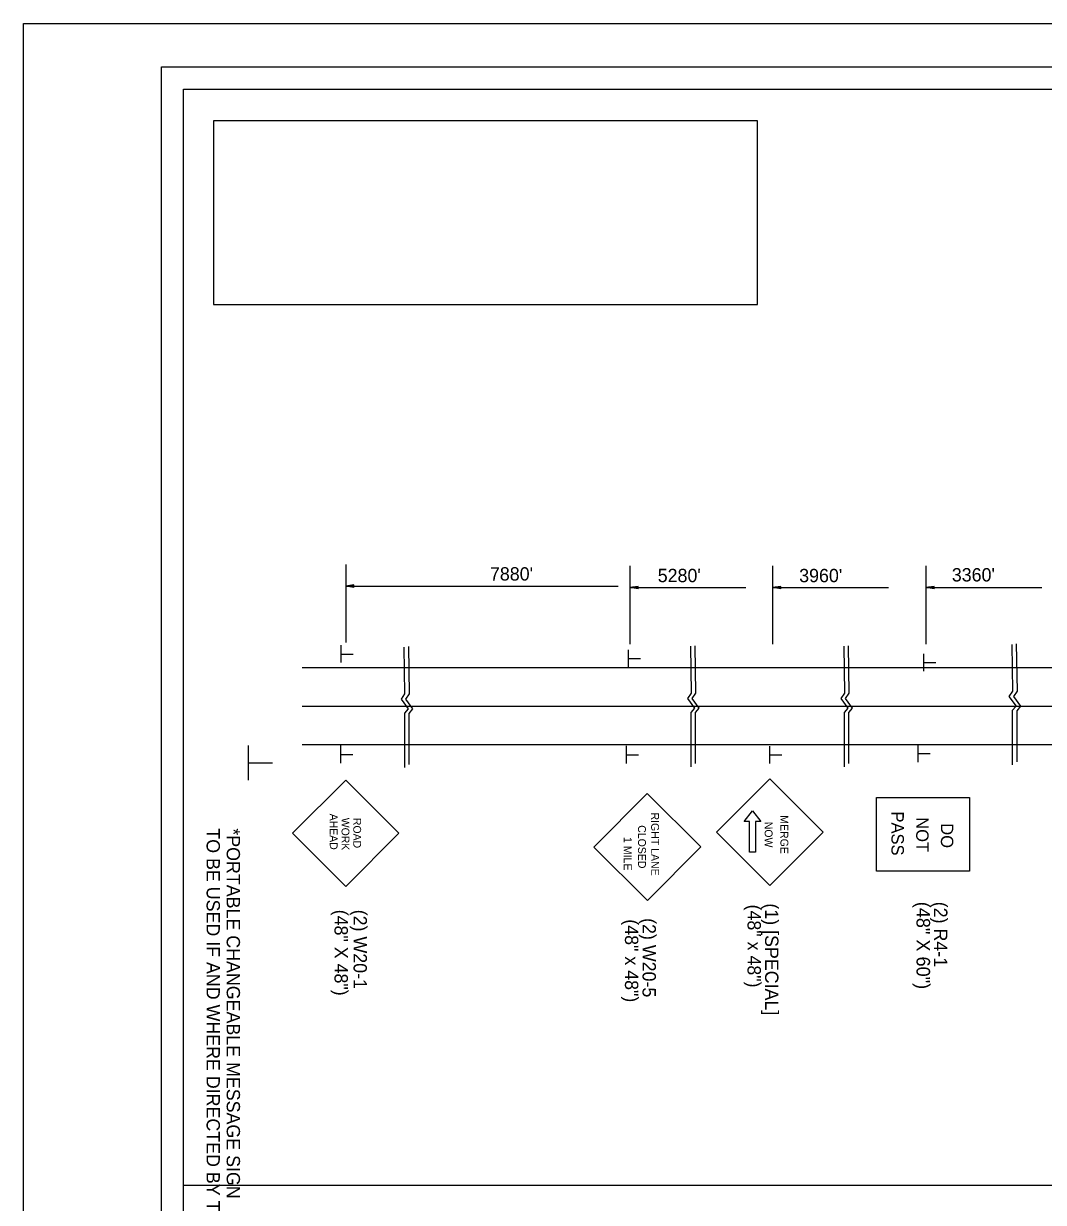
# Model space of a CAD drawing. Extents: x -500 to 213, y 382723 to 382830.
# Drawn here: x -316.3 to -270.4, y 382776.7 to 382829.8 of the extents above; entities that cross this region are included whole.
import ezdxf

# ---------------------------------------------------------------- set-up
doc = ezdxf.new("R2010")
doc.units = 0
for name, color, linetype in [('Default', 7, 'Continuous'), ('R_Border', 7, 'Continuous'), ('R_Draft', 7, 'Continuous'), ('R_No Plot', 7, 'Continuous')]:
    doc.layers.add(name, color=color, linetype=linetype)

msp = doc.modelspace()

# ---------------------------------------------------------------- linework, layer by layer
at = {"layer": 'Default'}
for p, q in [((-301.787, 382805.446), (-301.787, 382801.925)), ((-288.995, 382805.379), (-288.995, 382801.858)), ((-282.579, 382805.379), (-282.579, 382801.858)), ((-275.679, 382805.379), (-275.679, 382801.858)), ((-301.412, 382804.523), (-301.787, 382804.466)), ((-301.787, 382804.466), (-289.524, 382804.466)), ((-301.412, 382804.41), (-301.787, 382804.466)), ((-301.412, 382804.513), (-301.725, 382804.466)), ((-301.412, 382804.42), (-301.725, 382804.466)), ((-301.412, 382804.504), (-301.66, 382804.466)), ((-301.412, 382804.429), (-301.66, 382804.466)), ((-301.412, 382804.494), (-301.598, 382804.466)), ((-301.412, 382804.439), (-301.598, 382804.466)), ((-301.412, 382804.485), (-301.534, 382804.466)), ((-301.412, 382804.448), (-301.534, 382804.466)), ((-301.412, 382804.475), (-301.472, 382804.466)), ((-301.412, 382804.458), (-301.472, 382804.466)), ((-301.412, 382804.41), (-301.412, 382804.523)), ((-288.62, 382804.456), (-288.995, 382804.4)), ((-288.995, 382804.4), (-283.776, 382804.4)), ((-288.62, 382804.344), (-288.995, 382804.4)), ((-288.62, 382804.447), (-288.933, 382804.4)), ((-288.62, 382804.353), (-288.933, 382804.4)), ((-288.62, 382804.437), (-288.868, 382804.4)), ((-288.62, 382804.363), (-288.868, 382804.4)), ((-288.62, 382804.428), (-288.806, 382804.4)), ((-288.62, 382804.372), (-288.806, 382804.4)), ((-288.62, 382804.418), (-288.742, 382804.4)), ((-288.62, 382804.382), (-288.742, 382804.4)), ((-288.62, 382804.409), (-288.679, 382804.4)), ((-288.62, 382804.391), (-288.679, 382804.4)), ((-288.62, 382804.344), (-288.62, 382804.456)), ((-282.204, 382804.456), (-282.579, 382804.4)), ((-282.579, 382804.4), (-277.36, 382804.4)), ((-282.204, 382804.344), (-282.579, 382804.4)), ((-282.204, 382804.447), (-282.517, 382804.4)), ((-282.204, 382804.353), (-282.517, 382804.4)), ((-282.204, 382804.437), (-282.452, 382804.4)), ((-282.204, 382804.363), (-282.452, 382804.4)), ((-282.204, 382804.428), (-282.39, 382804.4)), ((-282.204, 382804.372), (-282.39, 382804.4)), ((-282.204, 382804.418), (-282.326, 382804.4)), ((-282.204, 382804.382), (-282.326, 382804.4)), ((-282.204, 382804.409), (-282.263, 382804.4)), ((-282.204, 382804.391), (-282.263, 382804.4)), ((-282.204, 382804.344), (-282.204, 382804.456)), ((-275.304, 382804.456), (-275.679, 382804.4)), ((-275.679, 382804.4), (-270.46, 382804.4)), ((-275.304, 382804.344), (-275.679, 382804.4)), ((-275.304, 382804.447), (-275.616, 382804.4)), ((-275.304, 382804.353), (-275.616, 382804.4)), ((-275.304, 382804.437), (-275.552, 382804.4)), ((-275.304, 382804.363), (-275.552, 382804.4)), ((-275.304, 382804.428), (-275.489, 382804.4)), ((-275.304, 382804.372), (-275.489, 382804.4)), ((-275.304, 382804.418), (-275.426, 382804.4)), ((-275.304, 382804.382), (-275.426, 382804.4)), ((-275.304, 382804.409), (-275.363, 382804.4)), ((-275.304, 382804.391), (-275.363, 382804.4)), ((-275.304, 382804.344), (-275.304, 382804.456)), ((-301.995, 382801.022), (-301.995, 382801.805)), ((-289.057, 382800.814), (-289.057, 382801.597)), ((-275.77, 382800.644), (-275.77, 382801.427)), ((-301.984, 382801.412), (-301.45, 382801.412)), ((-289.046, 382801.203), (-288.512, 382801.203)), ((-275.758, 382801.033), (-275.224, 382801.033)), ((-303.739, 382800.808), (-296.862, 382800.808)), ((-296.862, 382800.808), (-293.436, 382800.808)), ((-293.436, 382800.808), (-286.775, 382800.808)), ((-286.775, 382800.808), (-279.874, 382800.808)), ((-279.874, 382800.808), (-272.48, 382800.808)), ((-272.48, 382800.808), (-266.283, 382800.808)), ((-303.739, 382799.07), (-296.785, 382799.07)), ((-296.785, 382799.07), (-292.892, 382799.07)), ((-292.892, 382799.07), (-286.775, 382799.07)), ((-286.775, 382799.07), (-279.874, 382799.07)), ((-279.874, 382799.07), (-272.434, 382799.07)), ((-272.434, 382799.07), (-266.317, 382799.07)), ((-306.167, 382795.726), (-306.167, 382797.291)), ((-303.739, 382797.331), (-296.856, 382797.331)), ((-302.005, 382796.504), (-302.005, 382797.287)), ((-296.856, 382797.331), (-293.431, 382797.331)), ((-293.431, 382797.331), (-286.775, 382797.331)), ((-289.154, 382796.488), (-289.154, 382797.27)), ((-286.775, 382797.331), (-279.874, 382797.331)), ((-282.694, 382796.482), (-282.694, 382797.265)), ((-279.874, 382797.331), (-272.388, 382797.331)), ((-276.027, 382796.539), (-276.027, 382797.321)), ((-272.388, 382797.331), (-266.351, 382797.331)), ((-301.993, 382796.893), (-301.459, 382796.893)), ((-289.142, 382796.877), (-288.608, 382796.877)), ((-282.683, 382796.871), (-282.149, 382796.871)), ((-276.016, 382796.928), (-275.482, 382796.928)), ((-306.144, 382796.505), (-305.076, 382796.505)), ((-304.173, 382793.34), (-301.784, 382795.73)), ((-299.394, 382793.34), (-301.784, 382795.73)), ((-285.101, 382793.384), (-282.7, 382795.794)), ((-280.292, 382793.393), (-282.7, 382795.794)), ((-290.618, 382792.721), (-288.216, 382795.131)), ((-285.808, 382792.729), (-288.216, 382795.131)), ((-283.851, 382793.869), (-283.476, 382794.356)), ((-283.476, 382794.356), (-283.101, 382793.869)), ((-283.617, 382793.869), (-283.851, 382793.869)), ((-283.617, 382792.49), (-283.617, 382793.869)), ((-283.335, 382793.869), (-283.335, 382792.49)), ((-283.101, 382793.869), (-283.335, 382793.869)), ((-301.784, 382790.95), (-304.173, 382793.34)), ((-301.784, 382790.95), (-299.394, 382793.34)), ((-282.691, 382790.983), (-285.101, 382793.384)), ((-282.691, 382790.983), (-280.292, 382793.393)), ((-288.208, 382790.32), (-290.618, 382792.721)), ((-288.208, 382790.32), (-285.808, 382792.729)), ((-283.335, 382792.49), (-283.617, 382792.49))]:
    msp.add_line(p, q, dxfattribs=at)
for points in [[(-299.164, 382801.724), (-299.132, 382799.621), (-299.294, 382799.379), (-298.978, 382798.946), (-299.145, 382798.747), (-299.145, 382796.301)], [(-298.965, 382801.743), (-298.932, 382799.613), (-299.095, 382799.371), (-298.778, 382798.938), (-298.945, 382798.738), (-298.945, 382796.441)], [(-286.27, 382801.758), (-286.238, 382799.654), (-286.4, 382799.413), (-286.084, 382798.98), (-286.25, 382798.78), (-286.251, 382796.334)], [(-286.07, 382801.777), (-286.038, 382799.646), (-286.2, 382799.404), (-285.884, 382798.972), (-286.051, 382798.772), (-286.051, 382796.475)], [(-279.369, 382801.758), (-279.337, 382799.654), (-279.5, 382799.413), (-279.183, 382798.98), (-279.35, 382798.78), (-279.35, 382796.334)], [(-279.17, 382801.777), (-279.138, 382799.646), (-279.3, 382799.404), (-278.984, 382798.972), (-279.15, 382798.772), (-279.151, 382796.475)], [(-271.801, 382801.844), (-271.769, 382799.741), (-271.932, 382799.499), (-271.615, 382799.066), (-271.782, 382798.867), (-271.782, 382796.421)], [(-271.602, 382801.863), (-271.57, 382799.732), (-271.732, 382799.491), (-271.416, 382799.058), (-271.582, 382798.858), (-271.582, 382796.561)]]:
    msp.add_lwpolyline(points, dxfattribs=at)
msp.add_lwpolyline([(-273.713, 382791.637), (-277.895, 382791.637), (-277.895, 382794.955), (-273.713, 382794.955)], close=True, dxfattribs=at)
at = {"layer": 'R_Border'}
for p, q in [((-310.08, 382827.85), (-151.99, 382827.85)), ((-310.08, 382725.12), (-310.08, 382827.85))]:
    msp.add_line(p, q, dxfattribs=at)
at = {"layer": 'R_Draft'}
msp.add_lwpolyline([(-307.733, 382817.154), (-283.244, 382817.154), (-283.244, 382825.418), (-307.733, 382825.418)], close=True, dxfattribs=at)
at = {"layer": 'R_No Plot'}
for points in [[(-316.283, 382829.798), (-149.613, 382829.798), (-149.613, 382723.129), (-316.283, 382723.129)], [(-152.99, 382777.485), (-309.08, 382777.485), (-309.08, 382826.85), (-184.31, 382826.85), (-184.31, 382821.91), (-175.54, 382821.91), (-163.49, 382821.91), (-163.49, 382810.744), (-152.99, 382810.744)], [(-309.08, 382826.85), (-184.31, 382826.85), (-184.31, 382821.91), (-175.54, 382821.91), (-163.49, 382821.91), (-163.49, 382810.744), (-152.99, 382810.744), (-152.99, 382726.12), (-309.08, 382726.12)]]:
    msp.add_lwpolyline(points, close=True, dxfattribs=at)

# ---------------------------------------------------------------- texts
at = {"layer": 'Default'}
for s, p in [("7880'", (-295.293, 382804.72)), ("5280'", (-287.742, 382804.647)), ("3960'", (-281.375, 382804.645)), ("3360'", (-274.505, 382804.678))]:
    msp.add_text(s, height=0.6, dxfattribs=at).set_placement(p)
for s, height, rotation, p in [(' AHEAD', 0.3522, 270.0006, (-302.5, 382794.352)), ('WORK', 0.352, 270, (-301.972, 382794.038)), ('ROAD', 0.3521, 270.0004, (-301.444, 382794.031)), ('RIGHT LANE', 0.3544, 270.1004, (-288.038, 382794.275)), ('MERGE', 0.3544, 270.1004, (-282.22, 382794.151)), ('PASS', 0.5566, 270, (-277.221, 382794.322)), ('NOT', 0.5566, 270, (-276.108, 382794.063)), ('TO BE USED IF AND WHERE DIRECTED BY THE ENGINEER', 0.6, 270, (-308.048, 382793.562)), ('*PORTABLE CHANGEABLE MESSAGE SIGN', 0.6, 270, (-307.143, 382793.562)), ('CLOSED', 0.3543, 270.1003, (-288.628, 382793.703)), ('NOW', 0.3543, 270.1003, (-282.929, 382793.858)), ('DO', 0.5566, 270, (-274.995, 382793.791)), ('1 MILE', 0.3567, 270.0006, (-289.269, 382793.172)), ('(48" X 48")', 0.6, 270, (-302.289, 382789.898)), ('(2) W20-1', 0.6, 270, (-301.433, 382789.898)), ('(48" x 48")', 0.6, 270, (-283.699, 382790.13)), ('(1) [SPECIAL]', 0.6, 270, (-282.91, 382790.183)), ('(48" X 60")', 0.61, 270, (-276.094, 382790.256)), ('(2) R4-1', 0.6, 270, (-275.305, 382790.256)), ('(48" x 48")', 0.6, 270, (-289.216, 382789.466)), ('(2) W20-5', 0.6, 270, (-288.426, 382789.52))]:
    msp.add_text(s, height=height, rotation=rotation, dxfattribs=at).set_placement(p)

doc.saveas('drawing.dxf')
